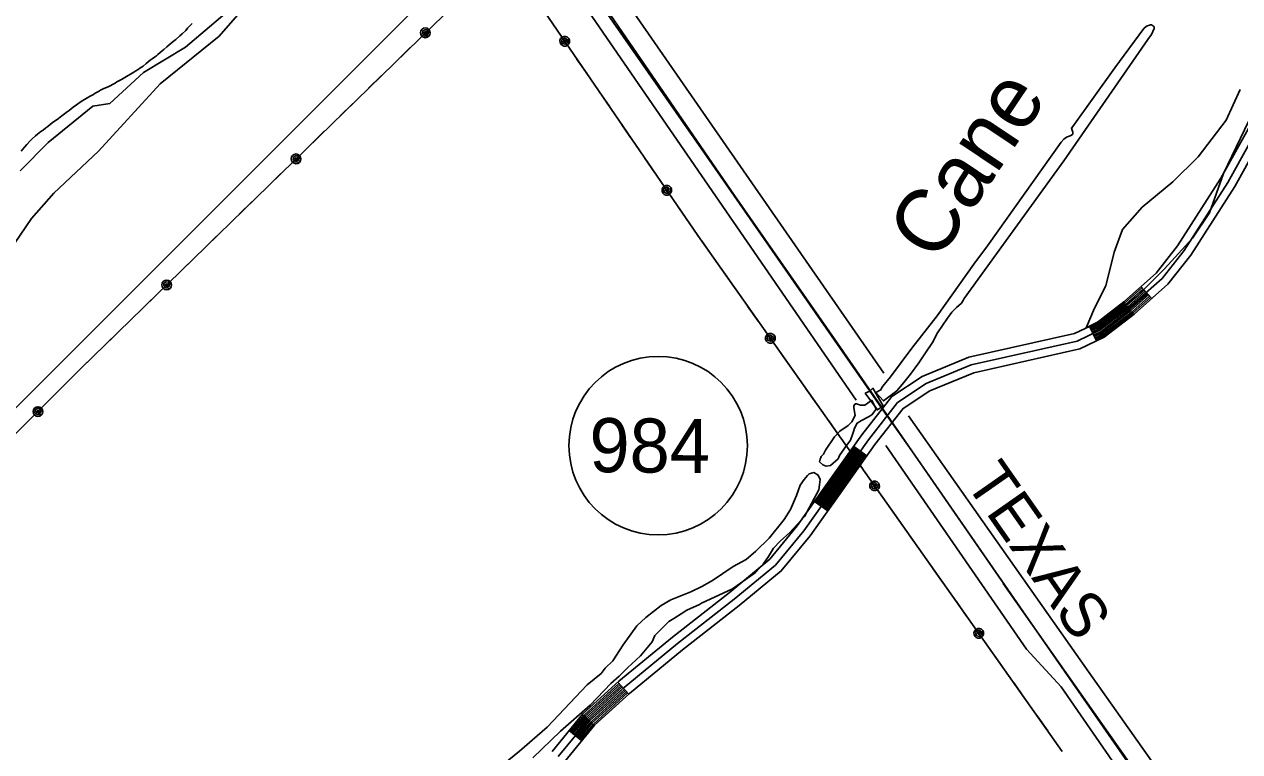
# Model space of a CAD drawing. Extents: x 3271442 to 3309282, y 752266 to 777610.
# Drawn here: x 3277086 to 3279334, y 765883 to 767228 of the extents above; entities that cross this region are included whole.
import ezdxf

# ---------------------------------------------------------------- set-up
doc = ezdxf.new("R2010")
doc.units = 0
for name, color, linetype in [('V-BRDG-OTLN', 7, 'Continuous'), ('V-RAIL-IDEN', 7, 'Continuous'), ('V-RAIL-TRAK', 7, 'Continuous'), ('V-RIVR-IDEN', 7, 'Continuous'), ('V-ROAD-CNTR', 7, 'Continuous'), ('V-ROAD-IDEN', 7, 'Continuous'), ('V-SITE-VEGE', 7, 'Continuous'), ('V-TOPO-BNDY', 7, 'Continuous'), ('V-TOPO-SHOR', 7, 'Continuous'), ('V-UTIL-LINE', 7, 'Continuous')]:
    doc.layers.add(name, color=color, linetype=linetype)

msp = doc.modelspace()

# ---------------------------------------------------------------- linework, layer by layer
at = {"layer": 'V-BRDG-OTLN'}
msp.add_lwpolyline([(3278641.4, 766546), (3278649.9, 766550.2), (3278655.5, 766555.2), (3278674.5, 766523), (3278663.7, 766515.3)], close=True, dxfattribs=at)
at = {"layer": 'V-RAIL-TRAK'}
msp.add_lwpolyline([(3276291.2, 769941.4), (3276466.8, 769687.9), (3276599.6, 769496.8), (3276819.8, 769181), (3277020, 768893.5), (3277174.1, 768671), (3277374.2, 768384.3), (3277564.8, 768110.1), (3277710.5, 767901.4), (3277897.5, 767631.8), (3278109.9, 767326.4), (3278338.2, 766998.2), (3278559.3, 766680.6), (3278649.4, 766551), (3278673.9, 766515.2), (3278727.5, 766439.3), (3278938.1, 766135.1), (3279106.8, 765892.9), (3279335.7, 765562.9), (3279510.8, 765302.4)], dxfattribs=at)
at = {"layer": 'V-ROAD-CNTR'}
for p, q in [((3279151.2, 766743.6), (3279171.1, 766721.1)), ((3279056.1, 766669.9), (3279068.9, 766642.8)), ((3278620, 766447.8), (3278644.5, 766430.5)), ((3278547.7, 766345.9), (3278572.1, 766328.5)), ((3278183.8, 766011.9), (3278203.9, 765989.6)), ((3278093.7, 765922.4), (3278116.9, 765903.4))]:
    msp.add_line(p, q, dxfattribs=at)
for points in [[(3275588.3, 770956.2), (3275688.4, 770811.8), (3276101.8, 770219.4), (3276456.7, 769703.3), (3276672.3, 769394.3), (3277041.1, 768858.2), (3277365.6, 768392.2), (3277712.8, 767894.2), (3278018.2, 767467.5), (3278399.6, 766911.8), (3278583.9, 766647.6), (3278893.1, 766199.7)], [(3278062, 765883.8), (3278119, 765953.1), (3278185.8, 766013.7), (3278284.8, 766095.3), (3278389.7, 766176.8), (3278464.8, 766239), (3278515.7, 766300.9), (3278635.1, 766469), (3278690.7, 766540.3), (3278746.7, 766577.2), (3278832.8, 766612.8), (3279028.5, 766656.8), (3279067.5, 766675.3), (3279119.4, 766715.4), (3279179.3, 766768.4), (3279219, 766818.9), (3279298.9, 766943.7), (3279383.3, 767095.5)], [(3279396.3, 767088.1), (3279311.8, 766936), (3279231.3, 766810.2), (3279190.2, 766758.1), (3279128.9, 766703.8), (3279075.4, 766662.5), (3279033.4, 766642.6), (3278837.3, 766598.5), (3278753.8, 766563.8), (3278701, 766529.1), (3278647.1, 766460.1), (3278527.7, 766291.8), (3278475.4, 766228.3), (3278399.1, 766165.1), (3278294.2, 766083.6), (3278195.6, 766002.3), (3278129.9, 765942.8), (3278073.6, 765874.2)], [(3278085.2, 765864.7), (3278140.8, 765932.4), (3278205.4, 765991), (3278303.5, 766071.9), (3278408.4, 766153.4), (3278486.1, 766217.7), (3278539.6, 766282.7), (3278659.1, 766451.1), (3278711.4, 766517.9), (3278760.8, 766550.5), (3278841.9, 766584.1), (3279038.3, 766628.3), (3279083.2, 766649.6), (3279138.5, 766692.2), (3279201.2, 766747.7), (3279243.5, 766801.5), (3279324.7, 766928.3), (3279409.4, 767080.7)], [(3279057.3, 766667.2), (3279069, 766672.7), (3279121.3, 766713.1), (3279153.2, 766741.3)], [(3279058.6, 766664.5), (3279070.6, 766670.2), (3279123.2, 766710.7), (3279155.2, 766739.1)], [(3279059.9, 766661.8), (3279072.2, 766667.6), (3279125.1, 766708.4), (3279157.2, 766736.8)], [(3279061.2, 766659.1), (3279073.8, 766665), (3279127, 766706.1), (3279159.2, 766734.6)], [(3279062.5, 766656.4), (3279075.4, 766662.5), (3279128.9, 766703.8), (3279161.2, 766732.4)], [(3279063.8, 766653.6), (3279076.9, 766659.9), (3279130.9, 766701.5), (3279163.2, 766730.1)], [(3279065.1, 766650.9), (3279078.5, 766657.3), (3279132.8, 766699.2), (3279165.2, 766727.9)], [(3279066.3, 766648.2), (3279080.1, 766654.7), (3279134.7, 766696.9), (3279167.2, 766725.6)], [(3279067.6, 766645.5), (3279081.7, 766652.2), (3279136.6, 766694.5), (3279169.1, 766723.4)], [(3278550.1, 766344.2), (3278622.5, 766446.1)], [(3278552.6, 766342.4), (3278624.9, 766444.4)], [(3278555, 766340.7), (3278627.4, 766442.6)], [(3278557.5, 766339), (3278629.8, 766440.9)], [(3278559.9, 766337.2), (3278632.3, 766439.1)], [(3278562.4, 766335.5), (3278634.7, 766437.4)], [(3278564.8, 766333.7), (3278637.2, 766435.7)], [(3278567.3, 766332), (3278639.6, 766433.9)], [(3278569.7, 766330.3), (3278642.1, 766432.2)], [(3278896.6, 766194.4), (3279207.3, 765753.2), (3279382, 765504.2), (3279510.2, 765320.4), (3279619.3, 765148.7), (3279740.6, 764957.9), (3279844.1, 764790.1), (3279937, 764634.6), (3280041, 764460.4), (3280130.2, 764309.9), (3280239.6, 764110.5), (3280361.9, 763885.2), (3280539.4, 763549), (3280924.1, 762814.5), (3281160.7, 762359.8), (3281314.6, 762065), (3281497.6, 761722.5), (3281661.2, 761410.7), (3281877.3, 760997.6)], [(3278096.1, 765920.5), (3278121.2, 765951.1), (3278185.8, 766009.6)], [(3278098.4, 765918.6), (3278123.3, 765949), (3278187.8, 766007.4)], [(3278100.7, 765916.7), (3278125.5, 765946.9), (3278189.8, 766005.2)], [(3278103, 765914.8), (3278127.7, 765944.8), (3278191.8, 766003)], [(3278105.3, 765912.9), (3278129.9, 765942.8), (3278193.8, 766000.8)], [(3278107.7, 765911), (3278132, 765940.7), (3278195.9, 765998.5)], [(3278110, 765909.1), (3278134.2, 765938.6), (3278197.9, 765996.3)], [(3278112.3, 765907.2), (3278136.4, 765936.6), (3278199.9, 765994.1)], [(3278114.6, 765905.3), (3278138.6, 765934.5), (3278201.9, 765991.9)]]:
    msp.add_lwpolyline(points, dxfattribs=at)
at = {"layer": 'V-ROAD-IDEN'}
msp.add_circle((3278258.3, 766449.3), 165, dxfattribs=at)
at = {"layer": 'V-SITE-VEGE'}
for points in [[(3277042.1, 767346.5), (3277088.8, 767346.5), (3277114.7, 767351.7), (3277145.8, 767372.4), (3277187.2, 767408.7), (3277207.9, 767429.5), (3277254.6, 767445), (3277321.9, 767455.4), (3277420.4, 767486.5), (3277503.3, 767517.6), (3277560.3, 767517.6), (3277612.1, 767502.1), (3277612.1, 767481.3), (3277591.4, 767450.2), (3277575.8, 767413.9), (3277549.9, 767351.7), (3277518.8, 767289.4), (3277446.3, 767206.5), (3277337.5, 767118.3), (3277223.5, 766993.8), (3277140.6, 766916.1), (3277099.1, 766869.4), (3277068.1, 766822.7)], [(3277078.4, 766957.5), (3277130.2, 767009.4), (3277213.1, 767076.8), (3277244.2, 767082), (3277306.4, 767139), (3277384.1, 767185.7), (3277456.7, 767247.9), (3277477.4, 767284.2), (3277487.7, 767330.9), (3277482.6, 767388), (3277482.6, 767408.7), (3277472.2, 767429.5), (3277456.7, 767439.8), (3277404.8, 767439.8), (3277363.4, 767429.5), (3277327.1, 767413.9), (3277290.8, 767393.2), (3277249.4, 767362), (3277207.9, 767336.1), (3277171.7, 767315.4), (3277125, 767310.2), (3277057.7, 767294.6)], [(3279366, 767082), (3279303.8, 766952.4), (3279277.9, 766879.8), (3279246.8, 766833.1), (3279195, 766776), (3279143.2, 766724.2), (3279091.4, 766687.9), (3279049.9, 766667.1), (3279065.5, 766703.4), (3279086.2, 766744.9), (3279101.7, 766807.2), (3279117.3, 766848.6), (3279153.5, 766890.1), (3279210.5, 766936.8), (3279257.2, 766983.5), (3279309, 767050.9), (3279334.9, 767107.9)]]:
    msp.add_lwpolyline(points, dxfattribs=at)
at = {"layer": 'V-TOPO-BNDY'}
msp.add_line((3279447.1, 768894.5), (3275720.8, 765171), dxfattribs=at)
at = {"layer": 'V-TOPO-SHOR'}
for p, q in [((3278050.2, 767485.2), (3278675.9, 766583.5)), ((3278624.7, 766533.1), (3277994.4, 767448.7)), ((3279209.4, 765705.6), (3279003.9, 766003.1))]:
    msp.add_line(p, q, dxfattribs=at)
for points in [[(3277396.8, 767229.9), (3277393.3, 767226.6), (3277388.1, 767220.9), (3277384.6, 767217.1), (3277378.2, 767210.9), (3277373.4, 767206.8), (3277366.2, 767200.4), (3277361.2, 767196.5), (3277354, 767190.1), (3277349.8, 767186.5), (3277344.3, 767181.6), (3277341.3, 767179.2), (3277337.3, 767175.9), (3277333.1, 767172.5), (3277330.6, 767170.2), (3277326.6, 767167.4), (3277322.6, 767164.3), (3277319.1, 767161.7), (3277315.1, 767158.6), (3277311.4, 767156), (3277305.7, 767151.1), (3277299.9, 767147), (3277296.9, 767144.9), (3277292.2, 767142.1), (3277288.4, 767139.7), (3277282.2, 767136.1), (3277278.2, 767133.8), (3277271.7, 767130.1), (3277265.7, 767126.5), (3277261.9, 767124.6), (3277256.9, 767121.8), (3277254.2, 767119.5), (3277249.4, 767117.1), (3277246.2, 767115.3), (3277241.4, 767112.9), (3277233.1, 767109.5), (3277227.1, 767106.6), (3277223.4, 767104.3), (3277217.4, 767100.9), (3277213.9, 767098.6), (3277208.1, 767095.5), (3277203.8, 767093.1), (3277197.6, 767089.5), (3277193.1, 767086.6), (3277186.6, 767082.2), (3277182.6, 767079.1), (3277176.4, 767074.8), (3277172.6, 767071.9), (3277168.9, 767069.1), (3277163.6, 767065.2), (3277160.4, 767062.6), (3277155.7, 767059.3), (3277149.4, 767054.1), (3277144.9, 767051), (3277140.2, 767047.9), (3277134.5, 767043.8), (3277129.5, 767039.4), (3277126, 767036.8), (3277120.8, 767032.4), (3277116.5, 767029.8), (3277110.5, 767025.4), (3277106.8, 767022.1), (3277100.6, 767016.7), (3277096.8, 767012.8), (3277090.6, 767006.2), (3277086.2, 767001.3), (3277080.5, 766993.4)], [(3278721.5, 766504.6), (3279054.9, 766030.4), (3279475.2, 765435.4), (3279543.7, 765333.2), (3279571.2, 765309.8), (3279589.4, 765272.7), (3279685.2, 765119.4)], [(3278679.4, 766449.5), (3278939.8, 766073), (3279003.9, 766003.1)], [(3278026.7, 765872), (3278077.9, 765921.2), (3278132.7, 765969.2), (3278170.8, 766009.1), (3278186.3, 766023.1), (3278201.8, 766038.4), (3278225.6, 766060.6), (3278247.1, 766086.4), (3278251.9, 766098.2), (3278278.1, 766124), (3278287.6, 766129.8), (3278300.7, 766138), (3278311.3, 766145), (3278335.1, 766155.4), (3278338.6, 766157.8), (3278395.6, 766184.5), (3278438.4, 766214.8), (3278452.7, 766230.1), (3278462.2, 766244.2), (3278471.8, 766259.5), (3278483.7, 766272.4), (3278501.6, 766288.8), (3278514.7, 766302.8), (3278529, 766318.1), (3278555.4, 766367.5), (3278556.7, 766376.9), (3278557.9, 766386.4), (3278554.5, 766394.7), (3278546.2, 766399.5), (3278537.9, 766397.2), (3278534.4, 766393.7), (3278528.4, 766386.6), (3278521.2, 766376), (3278514, 766357.2), (3278503.1, 766331.3), (3278491.1, 766312.5), (3278463.7, 766278.4), (3278438.7, 766253.8), (3278420.8, 766238.6), (3278397.1, 766225.8), (3278359.1, 766200.1), (3278338.9, 766188.5), (3278318.7, 766179.2), (3278282, 766164.1), (3278264.2, 766153.7), (3278235.6, 766131.4), (3278218.9, 766116.2), (3278193.8, 766081), (3278174.7, 766051.6), (3278160.4, 766037.5), (3278153.2, 766028.1), (3278127.1, 766007.1), (3278053.1, 765928.5), (3278002, 765884), (3277955.6, 765846.6)]]:
    msp.add_lwpolyline(points, dxfattribs=at)
for points in [[(3278727.7, 766629.6), (3278688.3, 766576.7), (3278674, 766559.1), (3278671.6, 766555.6), (3278670.4, 766552.1), (3278660.9, 766547.4), (3278674.9, 766531.9), (3278699.9, 766550.6), (3278713, 766565.9), (3278725, 766581.2), (3278740.5, 766602.3), (3278752.5, 766621.1), (3278765.6, 766639.9), (3278775.2, 766657.5), (3278793.2, 766684.6), (3278801.5, 766696.3), (3278809.9, 766704.5), (3278819.4, 766712.7), (3278823, 766718.6), (3278824.2, 766721), (3279008.3, 766975.8), (3279163.7, 767200.3), (3279170.9, 767209.7), (3279175.7, 767220.2), (3279175.7, 767223.8), (3279175.7, 767223.8), (3279174.6, 767225), (3279171, 767227.4), (3279168.7, 767227.4), (3279161.6, 767225.1), (3279156.8, 767220.4), (3279103, 767147.6), (3279025.3, 767039.5), (3279022.9, 767036), (3279025.2, 767028.9), (3279025.2, 767027.7), (3279025.2, 767025.3), (3279022.8, 767023), (3279020.5, 767021.8), (3279013.3, 767019.5), (3279008.6, 767016), (3279003.8, 767010.2), (3278867.5, 766818.7), (3278842.4, 766784.6), (3278774.3, 766689.5)], [(3278653.7, 766533.3), (3278640.6, 766524), (3278639.4, 766524), (3278632.3, 766524), (3278625.3, 766526.4), (3278622.9, 766526.5), (3278620.5, 766522.9), (3278620.5, 766519.4), (3278622.7, 766505.2), (3278616.7, 766493.4), (3278609.6, 766486.4), (3278594.1, 766475.9), (3278584.6, 766465.3), (3278567.8, 766440.7), (3278564.2, 766433.6), (3278559.5, 766428.9), (3278558.2, 766424.2), (3278557, 766419.5), (3278562.9, 766413.5), (3278568.8, 766411.1), (3278577, 766412.2), (3278591.3, 766425.1), (3278593.7, 766431), (3278603.3, 766445.1), (3278614.1, 766459.2), (3278617.7, 766469.8), (3278620.1, 766476.9), (3278621.3, 766481.6), (3278626.1, 766491), (3278634.5, 766495.6), (3278647.5, 766502.6), (3278653.4, 766506.1), (3278661.8, 766516.7), (3278661.8, 766516.7), (3278660.6, 766519.1)]]:
    msp.add_lwpolyline(points, close=True, dxfattribs=at)
at = {"layer": 'V-UTIL-LINE'}
for points in [[(3279005.6, 765883.7), (3278331.7, 766837.7), (3277994.9, 767329.3), (3277631.8, 767852), (3277284.6, 768345), (3276919.6, 768869.7), (3276565.6, 769367.2), (3276205.7, 769892.6), (3275850.4, 770416.7), (3275590.6, 770788.1)], [(3275590.5, 770624.9), (3276059.5, 769948.1), (3276674.4, 769066.4), (3277292.2, 768190.2), (3277909.2, 767291.7), (3277189.9, 766591.1), (3276455.4, 765855.4), (3275722.9, 765125.4), (3275589.7, 764926.7)], [(3277827.9, 767212.5), (3277830.7, 767212), (3277829.7, 767214.1), (3277827, 767214.5), (3277825.2, 767212.3), (3277827.4, 767209.7), (3277832.1, 767209.6), (3277833.6, 767213.5), (3277831.3, 767217.8), (3277826.7, 767218.1), (3277822.9, 767215.7), (3277822.4, 767210.9), (3277826, 767206.8), (3277834.1, 767206.1), (3277836.1, 767209), (3277836.9, 767212.4), (3277836.2, 767215.8), (3277834.3, 767218.8), (3277831.4, 767220.8), (3277828, 767221.5), (3277824.5, 767220.9), (3277821.6, 767219), (3277819.6, 767216.1), (3277818.9, 767212.6), (3277819.5, 767209.2), (3277821.4, 767206.2), (3277824.3, 767204.2), (3277827.7, 767203.5), (3277831.2, 767204.2), (3277834.1, 767206.1)], [(3278085.6, 767196.9), (3278086.6, 767199.6), (3278084.4, 767199), (3278083.4, 767196.4), (3278085.4, 767194.2), (3278088.2, 767196), (3278089.2, 767200.6), (3278085.6, 767202.8), (3278081, 767201.2), (3278079.9, 767196.8), (3278081.6, 767192.6), (3278086.2, 767191.3), (3278090.9, 767194.1), (3278093, 767202), (3278090.5, 767204.4), (3278087.2, 767205.8), (3278083.7, 767205.7), (3278080.5, 767204.3), (3278078, 767201.8), (3278076.7, 767198.6), (3278076.8, 767195), (3278078.2, 767191.8), (3278080.7, 767189.4), (3278083.9, 767188.1), (3278087.4, 767188.1), (3278090.7, 767189.5), (3278093.1, 767192), (3278094.4, 767195.3), (3278094.4, 767198.8), (3278093, 767202)], [(3277799.9, 767185.3), (3277775.6, 767161.6)], [(3278107.6, 767164.7), (3278126.8, 767136.7)], [(3277746.9, 767133.7), (3277722.6, 767109.9)], [(3278149.5, 767103.7), (3278168.7, 767075.6)], [(3277693.9, 767082), (3277669.6, 767058.3)], [(3278191.3, 767042.6), (3278210.5, 767014.6)], [(3277640.9, 767030.4), (3277616.5, 767006.7)], [(3277588.6, 766979.5), (3277591.4, 766978.9), (3277590.5, 766981), (3277587.8, 766981.5), (3277585.9, 766979.2), (3277588.2, 766976.7), (3277592.9, 766976.5), (3277594.4, 766980.5), (3277592, 766984.8), (3277587.5, 766985), (3277583.7, 766982.7), (3277583.2, 766977.9), (3277586.8, 766973.7), (3277594.9, 766973), (3277596.9, 766975.9), (3277597.6, 766979.3), (3277597, 766982.8), (3277595, 766985.7), (3277592.2, 766987.7), (3277588.7, 766988.5), (3277585.3, 766987.8), (3277582.3, 766985.9), (3277580.3, 766983), (3277579.6, 766979.6), (3277580.2, 766976.1), (3277582.2, 766973.2), (3277585, 766971.2), (3277588.5, 766970.5), (3277591.9, 766971.1), (3277594.9, 766973)], [(3278233.1, 766981.6), (3278252.3, 766953.5)], [(3277560.7, 766952.2), (3277536.3, 766928.5)], [(3278274.3, 766921.4), (3278275.4, 766924), (3278273.1, 766923.5), (3278272.2, 766920.9), (3278274.1, 766918.7), (3278277, 766920.5), (3278278, 766925), (3278274.3, 766927.2), (3278269.7, 766925.7), (3278268.6, 766921.2), (3278270.3, 766917.1), (3278275, 766915.7), (3278279.7, 766918.6), (3278281.8, 766926.4), (3278279.3, 766928.9), (3278276, 766930.2), (3278272.5, 766930.2), (3278269.3, 766928.8), (3278266.8, 766926.3), (3278265.5, 766923), (3278265.5, 766919.5), (3278266.9, 766916.3), (3278269.4, 766913.8), (3278272.7, 766912.5), (3278276.2, 766912.6), (3278279.4, 766913.9), (3278281.9, 766916.4), (3278283.2, 766919.7), (3278283.1, 766923.2), (3278281.8, 766926.4)], [(3277507.7, 766900.6), (3277483.3, 766876.9)], [(3278296.4, 766889.2), (3278315.6, 766861.1)], [(3277454.7, 766849), (3277430.3, 766825.3)], [(3278338.3, 766828.2), (3278358, 766800.4)], [(3277401.6, 766797.3), (3277377.3, 766773.6)], [(3278381, 766767.8), (3278400.7, 766740)], [(3277349.4, 766746.4), (3277352.2, 766745.9), (3277351.2, 766748), (3277348.5, 766748.4), (3277346.7, 766746.2), (3277348.9, 766743.6), (3277353.6, 766743.5), (3277355.1, 766747.4), (3277352.8, 766751.7), (3277348.2, 766752), (3277344.4, 766749.6), (3277343.9, 766744.8), (3277347.5, 766740.7), (3277355.6, 766740), (3277357.6, 766742.9), (3277358.3, 766746.3), (3277357.7, 766749.7), (3277355.8, 766752.7), (3277352.9, 766754.7), (3277349.5, 766755.4), (3277346, 766754.8), (3277343.1, 766752.9), (3277341.1, 766750), (3277340.4, 766746.5), (3277341, 766743.1), (3277342.9, 766740.1), (3277345.8, 766738.1), (3277349.2, 766737.4), (3277352.7, 766738), (3277355.6, 766740)], [(3277321.4, 766719.2), (3277297.1, 766695.5)], [(3278423.7, 766707.3), (3278443.4, 766679.6)], [(3277268.4, 766667.6), (3277244.1, 766643.8)], [(3278465.9, 766647.7), (3278466.8, 766650.4), (3278464.6, 766649.8), (3278463.7, 766647.2), (3278465.7, 766645), (3278468.5, 766646.9), (3278469.4, 766651.5), (3278465.7, 766653.6), (3278461.2, 766652), (3278460.2, 766647.5), (3278461.9, 766643.4), (3278466.5, 766642.1), (3278471.2, 766645), (3278473.2, 766652.9), (3278470.7, 766655.3), (3278467.4, 766656.6), (3278463.9, 766656.5), (3278460.7, 766655.1), (3278458.2, 766652.5), (3278457, 766649.3), (3278457.1, 766645.7), (3278458.5, 766642.5), (3278461, 766640.1), (3278464.3, 766638.9), (3278467.8, 766638.9), (3278471, 766640.4), (3278473.5, 766642.9), (3278474.7, 766646.2), (3278474.6, 766649.7), (3278473.2, 766652.9)], [(3277215.4, 766615.9), (3277191, 766592.2)], [(3278488.4, 766615.9), (3278508, 766588.1)], [(3277162.8, 766563.9), (3277138.8, 766539.9)], [(3278531.1, 766555.4), (3278550.7, 766527.6)], [(3277111.2, 766512.2), (3277114, 766511.7), (3277113.1, 766513.8), (3277110.3, 766514.3), (3277108.5, 766512), (3277110.8, 766509.5), (3277115.5, 766509.4), (3277117, 766513.4), (3277114.6, 766517.6), (3277110, 766517.8), (3277106.2, 766515.4), (3277105.8, 766510.6), (3277109.4, 766506.5), (3277117.6, 766505.9), (3277119.5, 766508.8), (3277120.2, 766512.3), (3277119.5, 766515.7), (3277117.6, 766518.6), (3277114.6, 766520.6), (3277111.2, 766521.2), (3277107.7, 766520.6), (3277104.8, 766518.6), (3277102.9, 766515.7), (3277102.2, 766512.2), (3277102.9, 766508.8), (3277104.8, 766505.9), (3277107.8, 766503.9), (3277111.2, 766503.2), (3277114.6, 766503.9), (3277117.6, 766505.9)], [(3278573.8, 766495), (3278593.4, 766467.2)], [(3278616.5, 766434.5), (3278636.1, 766406.8)], [(3278658.6, 766374.9), (3278659.5, 766377.6), (3278657.3, 766377), (3278656.4, 766374.4), (3278658.4, 766372.2), (3278661.2, 766374.1), (3278662.1, 766378.7), (3278658.4, 766380.8), (3278653.9, 766379.2), (3278652.9, 766374.7), (3278654.6, 766370.6), (3278659.3, 766369.3), (3278663.9, 766372.2), (3278665.9, 766380.1), (3278663.4, 766382.5), (3278660.1, 766383.8), (3278656.6, 766383.7), (3278653.4, 766382.3), (3278651, 766379.7), (3278649.7, 766376.5), (3278649.8, 766372.9), (3278651.2, 766369.7), (3278653.8, 766367.3), (3278657, 766366.1), (3278660.5, 766366.2), (3278663.8, 766367.6), (3278666.2, 766370.1), (3278667.4, 766373.4), (3278667.3, 766376.9), (3278665.9, 766380.1)], [(3278681.1, 766343.1), (3278700.7, 766315.3)], [(3278723.8, 766282.6), (3278743.4, 766254.9)], [(3278766.5, 766222.2), (3278786.1, 766194.4)], [(3278809.2, 766161.7), (3278828.8, 766134)], [(3278851.3, 766102.1), (3278852.3, 766104.8), (3278850, 766104.2), (3278849.1, 766101.6), (3278851.1, 766099.4), (3278853.9, 766101.3), (3278854.8, 766105.9), (3278851.2, 766108), (3278846.6, 766106.4), (3278845.6, 766101.9), (3278847.3, 766097.8), (3278852, 766096.5), (3278856.6, 766099.4), (3278858.6, 766107.3), (3278856.1, 766109.7), (3278852.8, 766111), (3278849.3, 766110.9), (3278846.1, 766109.5), (3278843.7, 766106.9), (3278842.4, 766103.7), (3278842.5, 766100.1), (3278843.9, 766096.9), (3278846.5, 766094.5), (3278849.7, 766093.3), (3278853.3, 766093.4), (3278856.5, 766094.8), (3278858.9, 766097.3), (3278860.1, 766100.6), (3278860.1, 766104.1), (3278858.6, 766107.3)], [(3278873.8, 766070.3), (3278893.4, 766042.5)], [(3278916.5, 766009.8), (3278936.1, 765982.1)], [(3278959.2, 765949.4), (3278978.8, 765921.6)], [(3279001.9, 765888.9), (3279005.6, 765883.7)]]:
    msp.add_lwpolyline(points, dxfattribs=at)

# ---------------------------------------------------------------- texts
at = {"layer": 'V-RAIL-IDEN'}
msp.add_text('TEXAS', height=83, rotation=304.9484, dxfattribs=at).set_placement((3278824, 766381.6))
at = {"layer": 'V-RIVR-IDEN'}
msp.add_text('Cane', height=116, rotation=56.1487, dxfattribs=at).set_placement((3278773, 766784.7))
at = {"layer": 'V-ROAD-IDEN'}
msp.add_text('984', height=100, rotation=359.5282, dxfattribs=at).set_placement((3278130.8, 766400.3))

doc.saveas('drawing.dxf')
